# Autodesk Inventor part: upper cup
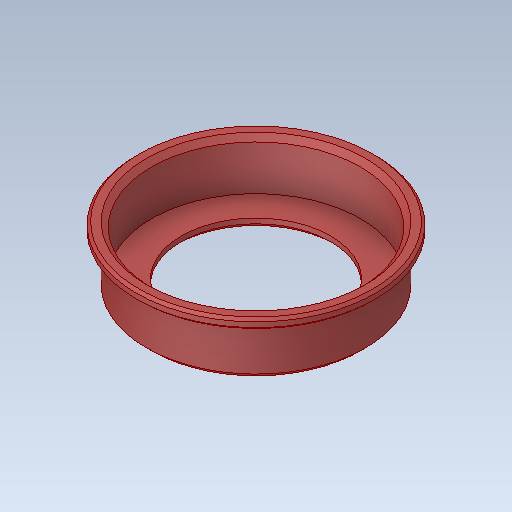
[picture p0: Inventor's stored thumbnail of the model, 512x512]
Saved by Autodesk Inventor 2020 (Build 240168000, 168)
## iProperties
Created: 2015-11
Part Number: upper cup
Material: Ogólny
Document SubType Name: Modeling
Designer: Tomasz
Density: 1 g/cm^3
Appearance: Domyślna
Sending System: SolidWorks 2017
Last Author: Tomasz
Last Saved: 2017-09-26
Author: Tomasz
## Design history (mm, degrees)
feature "Imported1"
node "Bryła1"
